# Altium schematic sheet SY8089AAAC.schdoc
size 127 x 101 mm
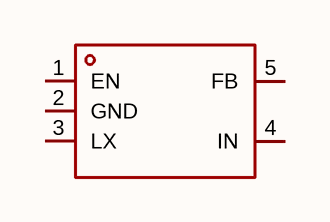
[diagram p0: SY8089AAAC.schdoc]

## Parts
U?  sy8089aaac  [SOT-23-5_L3.0-W1.7-P0.95-LS2.8-BR]  (value not drawn)

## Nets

Not connected (* = marked no-connect by the designer): U? 1(EN) 2(GND) 3(LX) 4(IN) 5(FB)

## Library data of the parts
U? = sy8089aaac: 功能类型:降压型;工作电压:2.7V~5.5V;输出电压:-;输出电流:2A;输出类型:可调;; Manufacturer: Silergy(矽力杰); AddInBom: yes; ModelId: 0a2a1b8f50944f73965918ad6e5fe167; ModelName: SOT-23-5_L2.9-W1.6-H1.1-LS2.8-P0.95; ModelTransform: 114.173,109.636,0,180,0,0,0,0,0; Function: 降压型; Output Current: 2A; Frequency - Switching: 1MHz; Synchronous Rectifier: 是; Number of Outputs: 1; Topology: 降压式; Quiescent Current: 55uA; Switch tube (built-in/external): 内置; Output Type: 可调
